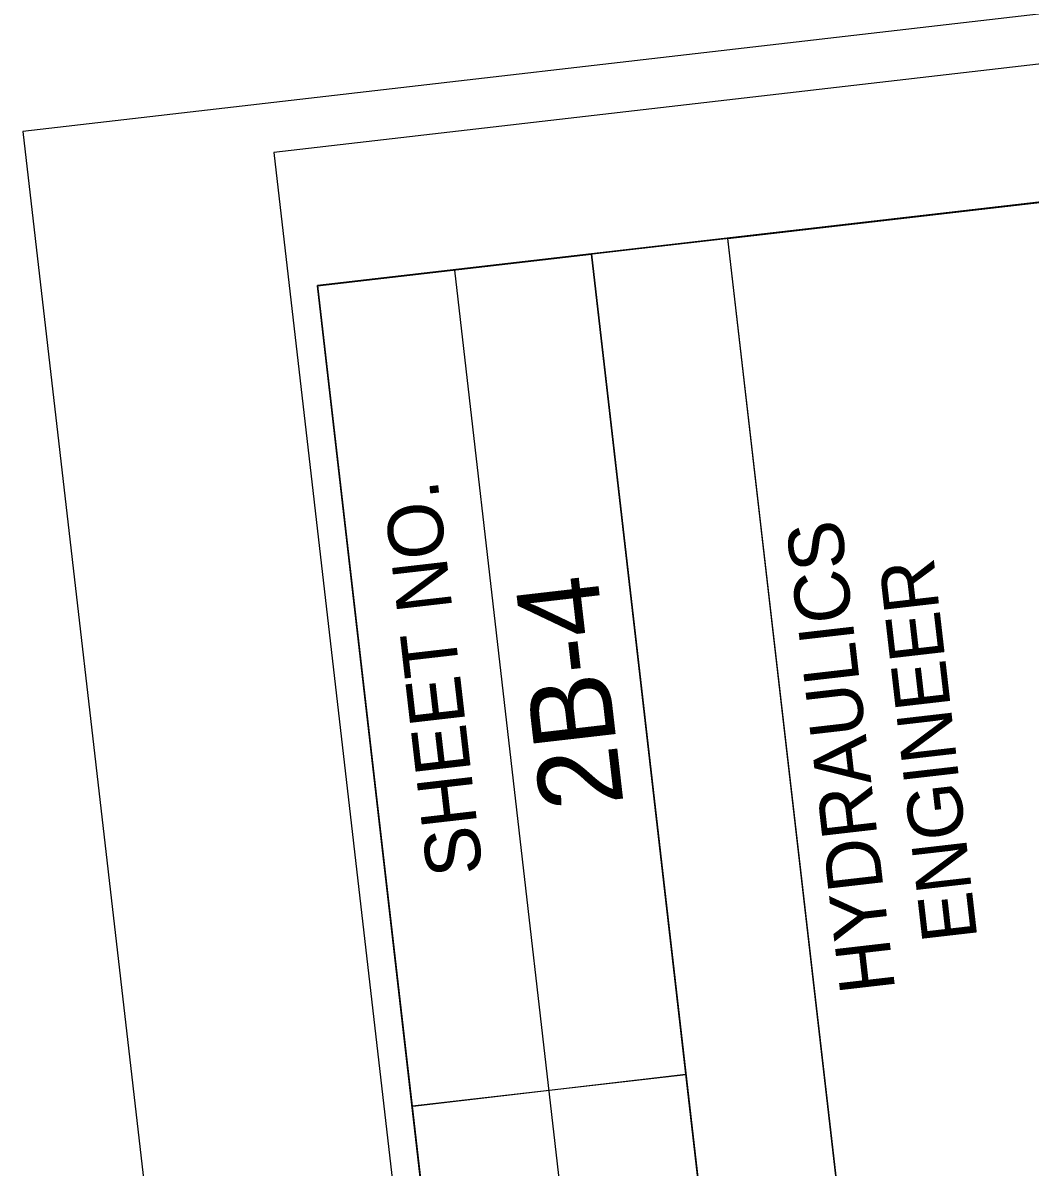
# Model space of a CAD drawing. Extents: x 477607 to 479438, y 495543 to 499482.
# Drawn here: x 477606.8 to 477698.4, y 497316 to 497419.9 of the extents above; entities that cross this region are included whole.
import ezdxf

# ---------------------------------------------------------------- set-up
doc = ezdxf.new("R2010")
doc.units = 0
for name, color, linetype in [('Sheet Border Standard 30in CELL', 7, 'Continuous'), ('Sheet Cutting Line CELL', 7, 'Continuous'), ('Sheet Data Field CELL', 7, 'Continuous'), ('Sheet Plan CELL', 7, 'Continuous'), ('Sheet Plot Border Inside CELL', 7, 'Continuous'), ('Sheet Plot Border Outside CELL', 7, 'Continuous')]:
    doc.layers.add(name, color=color, linetype=linetype)

msp = doc.modelspace()

# ---------------------------------------------------------------- linework, layer by layer
at = {"layer": 'Sheet Border Standard 30in CELL'}
for p, q in [((477681.41, 497200.18), (477658.5, 497398.91)), ((477681.41, 497200.18), (477658.5, 497398.91)), ((477668.99, 497198.75), (477646.08, 497397.48)), ((477642.25, 497321.54), (477667.09, 497324.41))]:
    msp.add_line(p, q, dxfattribs=at)
for points in [[(477633.61, 497396.04), (477805.43, 495905.92), (478848.52, 496026.19), (478676.7, 497516.31)], [(477682.37, 497301), (477670.91, 497400.34), (477782.67, 497413.23), (477794.13, 497313.89)], [(477656.53, 497197.31), (477633.61, 497396.04), (477658.5, 497398.91), (477681.41, 497200.18)]]:
    msp.add_lwpolyline(points, close=True, dxfattribs=at)
at = {"layer": 'Sheet Cutting Line CELL'}
msp.add_line((477606.83, 497410.07), (477799.72, 495737.15), dxfattribs=at)
at = {"layer": 'Sheet Plan CELL'}
for p, q in [((477681.43, 497200.19), (477658.5, 497398.91)), ((477681.43, 497200.19), (477658.5, 497398.91)), ((477668.98, 497198.75), (477646.08, 497397.48)), ((477642.27, 497321.52), (477667.1, 497324.43))]:
    msp.add_line(p, q, dxfattribs=at)
for points in [[(477633.61, 497396.08), (477805.43, 495905.92), (478848.52, 496026.19), (478676.7, 497516.33)], [(477682.38, 497301.02), (477670.91, 497400.34), (477782.68, 497413.24), (477794.15, 497313.9)], [(477656.51, 497197.32), (477633.61, 497396.08), (477658.5, 497398.91), (477681.43, 497200.19)]]:
    msp.add_lwpolyline(points, close=True, dxfattribs=at)
at = {"layer": 'Sheet Plot Border Inside CELL'}
msp.add_lwpolyline([(477629.65, 497408.17), (477820.53, 495752.64), (478868.69, 495873.49), (478677.8, 497529.02)], close=True, dxfattribs=at)
at = {"layer": 'Sheet Plot Border Outside CELL'}
msp.add_lwpolyline([(477606.83, 497410.07), (477799.72, 495737.15), (478892.48, 495863.15), (478699.59, 497536.07)], close=True, dxfattribs=at)

# ---------------------------------------------------------------- texts
at = {"layer": 'Sheet Border Standard 30in CELL'}
for s, p in [('SHEET NO.', (477648.62, 497342.71)), ('HYDRAULICS', (477686.13, 497332.09)), ('ENGINEER', (477693.6, 497336.77))]:
    msp.add_text(s, height=5, rotation=96.5773, dxfattribs=at).set_placement(p)
at = {"layer": 'Sheet Data Field CELL'}
msp.add_text('2B-4', height=7.5, rotation=96.5773, dxfattribs=at).set_placement((477661.44, 497348.97))
at = {"layer": 'Sheet Plan CELL'}
for s, p in [('SHEET NO.', (477648.64, 497342.74)), ('HYDRAULICS', (477686.12, 497332.11)), ('ENGINEER', (477693.6, 497336.76))]:
    msp.add_text(s, height=5, rotation=96.5773, dxfattribs=at).set_placement(p)

doc.saveas('drawing.dxf')
